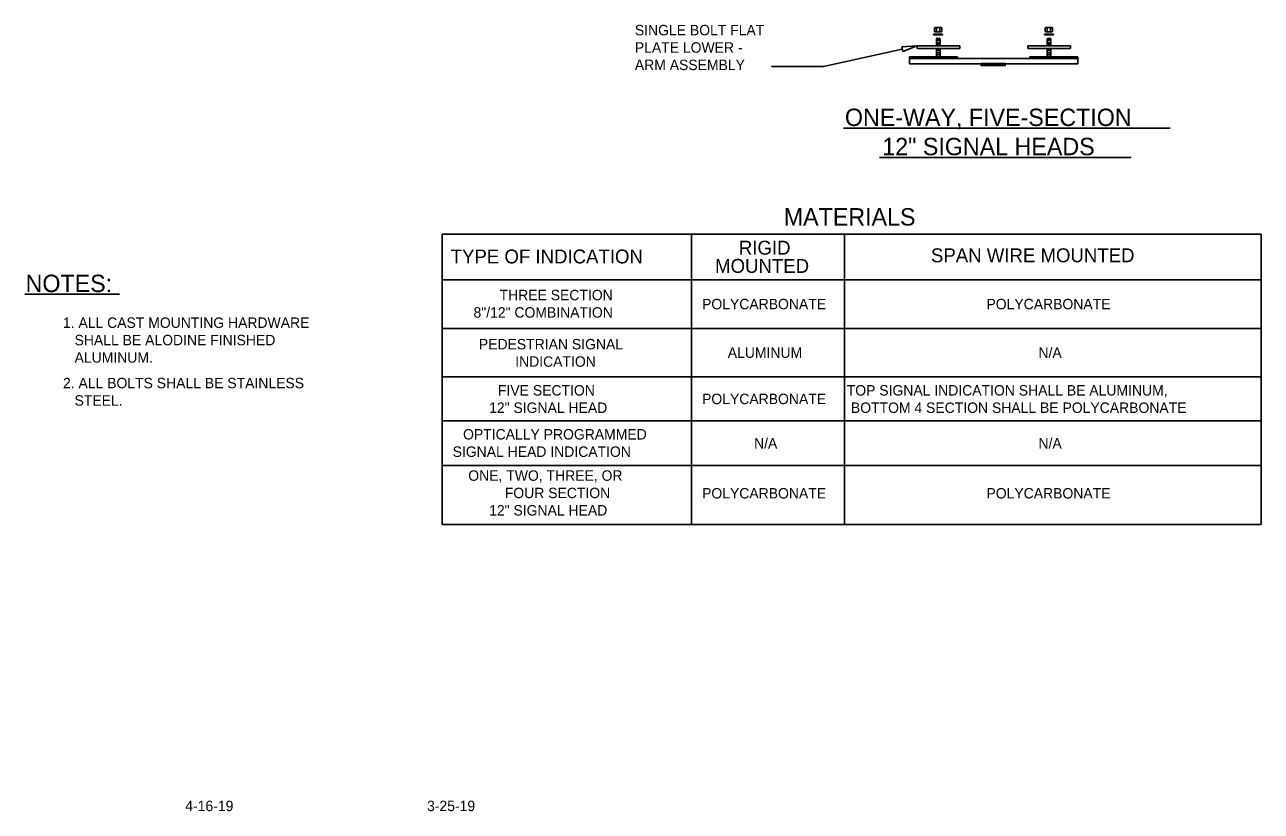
# Model space of a CAD drawing. Extents: x -1316.3 to -1303.1, y 2853.3 to 2863.3.
# Drawn here: x -1316.26 to -1309.14, y 2853.47 to 2857.99 of the extents above; entities that cross this region are included whole.
import ezdxf

# ---------------------------------------------------------------- set-up
doc = ezdxf.new("R2010")
doc.units = 0
for name, color, linetype in [('DETL-DIMS', 7, 'Continuous'), ('DETL-LINE', 7, 'Continuous'), ('DETL-NOTE', 7, 'Continuous'), ('DETL-TITL', 7, 'Continuous'), ('TTLB-TEXT', 7, 'Continuous')]:
    doc.layers.add(name, color=color, linetype=linetype)

msp = doc.modelspace()

# ---------------------------------------------------------------- linework, layer by layer
at = {"layer": 'DETL-DIMS'}
for p, q in [((-1311.2075, 2857.8542), (-1311.6607, 2857.7546)), ((-1311.6607, 2857.7546), (-1311.9592, 2857.7546))]:
    msp.add_line(p, q, dxfattribs=at)
for points in [[(-1311.2107, 2857.8682), (-1311.2043, 2857.8402), (-1311.1219, 2857.873)], [(-1310.7547, 2857.7714), (-1310.6155, 2857.7714), (-1310.6155, 2857.7594), (-1310.7547, 2857.7594)]]:
    msp.add_lwpolyline(points, close=True, dxfattribs=at)
at = {"layer": 'DETL-LINE'}
for p, q in [((-1311.0275, 2857.9402), (-1311.0275, 2857.937)), ((-1311.0275, 2857.9402), (-1310.9755, 2857.9402)), ((-1311.0275, 2857.937), (-1310.9755, 2857.937)), ((-1311.0219, 2857.9762), (-1311.0219, 2857.9562)), ((-1311.0195, 2857.9786), (-1310.9827, 2857.9786)), ((-1311.0195, 2857.9538), (-1310.9827, 2857.9538)), ((-1311.0115, 2857.873), (-1311.0115, 2857.9122)), ((-1311.0107, 2857.9786), (-1311.0107, 2857.9538)), ((-1311.0075, 2857.9162), (-1310.9955, 2857.9162)), ((-1310.9915, 2857.9786), (-1310.9915, 2857.9538)), ((-1310.9907, 2857.873), (-1310.9907, 2857.9122)), ((-1310.9803, 2857.9562), (-1310.9803, 2857.9762)), ((-1310.9755, 2857.9402), (-1310.9755, 2857.937)), ((-1310.3899, 2857.9402), (-1310.3387, 2857.9402)), ((-1310.3899, 2857.9402), (-1310.3899, 2857.937)), ((-1310.3899, 2857.937), (-1310.3387, 2857.937)), ((-1310.3851, 2857.9762), (-1310.3851, 2857.9562)), ((-1310.3827, 2857.9786), (-1310.3459, 2857.9786)), ((-1310.3827, 2857.9538), (-1310.3459, 2857.9538)), ((-1310.3747, 2857.873), (-1310.3747, 2857.9122)), ((-1310.3739, 2857.9786), (-1310.3739, 2857.9538)), ((-1310.3699, 2857.9162), (-1310.3579, 2857.9162)), ((-1310.3547, 2857.9786), (-1310.3547, 2857.9538)), ((-1310.3539, 2857.873), (-1310.3539, 2857.9122)), ((-1310.3435, 2857.9562), (-1310.3435, 2857.9762)), ((-1310.3387, 2857.9402), (-1310.3387, 2857.937)), ((-1311.1219, 2857.8578), (-1311.1219, 2857.873)), ((-1311.1219, 2857.873), (-1310.8771, 2857.873)), ((-1311.1219, 2857.8578), (-1310.8771, 2857.8578)), ((-1311.0115, 2857.905), (-1310.9907, 2857.905)), ((-1311.0115, 2857.893), (-1310.9907, 2857.893)), ((-1311.0115, 2857.8818), (-1310.9907, 2857.8818)), ((-1311.0115, 2857.8146), (-1311.0115, 2857.8578)), ((-1311.0115, 2857.8474), (-1310.9907, 2857.8474)), ((-1310.9907, 2857.8146), (-1310.9907, 2857.8578)), ((-1310.8771, 2857.8578), (-1310.8771, 2857.873)), ((-1310.4851, 2857.873), (-1310.2395, 2857.873)), ((-1310.4851, 2857.8578), (-1310.4851, 2857.873)), ((-1310.4851, 2857.8578), (-1310.2395, 2857.8578)), ((-1310.3747, 2857.905), (-1310.3539, 2857.905)), ((-1310.3747, 2857.893), (-1310.3539, 2857.893)), ((-1310.3747, 2857.8818), (-1310.3539, 2857.8818)), ((-1310.3747, 2857.8146), (-1310.3747, 2857.8578)), ((-1310.3747, 2857.8474), (-1310.3539, 2857.8474)), ((-1310.3539, 2857.8146), (-1310.3539, 2857.8578)), ((-1310.2395, 2857.8578), (-1310.2395, 2857.873)), ((-1311.1659, 2857.7698), (-1311.1659, 2857.8106)), ((-1311.1659, 2857.8106), (-1310.8891, 2857.8106)), ((-1311.1659, 2857.8002), (-1310.1971, 2857.8002)), ((-1311.1659, 2857.7698), (-1310.1971, 2857.7698)), ((-1311.0115, 2857.8354), (-1310.9907, 2857.8354)), ((-1311.0115, 2857.8242), (-1310.9907, 2857.8242)), ((-1311.0091, 2857.8122), (-1310.9931, 2857.8122)), ((-1310.8891, 2857.8002), (-1310.8891, 2857.8106)), ((-1310.4739, 2857.8002), (-1310.4739, 2857.8106)), ((-1310.4739, 2857.8106), (-1310.1971, 2857.8106)), ((-1310.3747, 2857.8354), (-1310.3539, 2857.8354)), ((-1310.3747, 2857.8242), (-1310.3539, 2857.8242)), ((-1310.3723, 2857.8122), (-1310.3555, 2857.8122)), ((-1310.1971, 2857.8106), (-1310.1971, 2857.7698))]:
    msp.add_line(p, q, dxfattribs=at)
for centre, radius, start, end in [((-1311.0196, 2857.9762), 0.00231, 90, 180), ((-1311.0196, 2857.9563), 0.00231, 180, 270), ((-1311.0071, 2857.9118), 0.00462, 90, 180), ((-1310.9956, 2857.9118), 0.00462, 0, 90), ((-1310.9828, 2857.9762), 0.00231, 0, 90), ((-1310.9828, 2857.9563), 0.00231, 270, 0), ((-1310.3827, 2857.9762), 0.00231, 90, 180), ((-1310.3827, 2857.9563), 0.00231, 180, 270), ((-1310.3697, 2857.9118), 0.00462, 90, 180), ((-1310.3581, 2857.9118), 0.00462, 0, 90), ((-1310.3459, 2857.9762), 0.00231, 0, 90), ((-1310.3459, 2857.9563), 0.00231, 270, 0), ((-1311.0094, 2857.8148), 0.00231, 180, 270), ((-1310.9933, 2857.8148), 0.00231, 270, 0), ((-1310.372, 2857.8148), 0.00231, 180, 270), ((-1310.3558, 2857.8148), 0.00231, 270, 0)]:
    msp.add_arc(centre, radius, start, end, dxfattribs=at)
at = {"layer": 'DETL-NOTE'}
for p, q in [((-1313.855, 2855.1203), (-1313.855, 2856.7894)), ((-1313.855, 2856.7894), (-1309.1427, 2856.7894)), ((-1312.4208, 2856.7894), (-1312.4208, 2855.1203)), ((-1311.5406, 2856.7894), (-1311.5406, 2855.1203)), ((-1309.1427, 2856.7894), (-1309.1427, 2855.1203)), ((-1313.855, 2856.5275), (-1309.1427, 2856.5275)), ((-1316.2556, 2856.4441), (-1315.7106, 2856.4441)), ((-1313.855, 2856.248), (-1309.1427, 2856.248)), ((-1313.855, 2855.9686), (-1309.1427, 2855.9686)), ((-1313.855, 2855.7154), (-1309.1427, 2855.7154)), ((-1309.1427, 2855.4583), (-1313.855, 2855.4583)), ((-1309.1427, 2855.1203), (-1313.855, 2855.1203))]:
    msp.add_line(p, q, dxfattribs=at)
at = {"layer": 'DETL-TITL'}
for p, q in [((-1311.5456, 2857.3994), (-1309.666, 2857.3994)), ((-1311.338, 2857.2314), (-1309.8913, 2857.2314))]:
    msp.add_line(p, q, dxfattribs=at)

# ---------------------------------------------------------------- texts
at = {"layer": 'DETL-NOTE'}
for s, height, p in [('SINGLE BOLT FLAT', 0.06, (-1312.746, 2857.9336)), ('PLATE LOWER -', 0.06, (-1312.746, 2857.8336)), ('ARM ASSEMBLY', 0.06, (-1312.746, 2857.7336)), ('MATERIALS', 0.1, (-1311.8896, 2856.8394)), ('RIGID', 0.08, (-1312.1478, 2856.672)), ('SPAN WIRE MOUNTED', 0.08, (-1311.0427, 2856.6282)), ('TYPE OF INDICATION', 0.08, (-1313.8053, 2856.6215)), ('MOUNTED', 0.08, (-1312.2845, 2856.5671)), ('NOTES:', 0.1, (-1316.2506, 2856.4566)), ('THREE SECTION', 0.06, (-1313.5241, 2856.4096)), ('POLYCARBONATE', 0.06, (-1312.3593, 2856.3577)), ('POLYCARBONATE', 0.06, (-1310.7234, 2856.3577)), ('8"/12" COMBINATION', 0.06, (-1313.6741, 2856.3096)), ('1. ALL CAST MOUNTING HARDWARE', 0.06, (-1316.0357, 2856.2506)), ('   SHALL BE ALODINE FINISHED', 0.06, (-1316.0357, 2856.1506)), ('PEDESTRIAN SIGNAL', 0.06, (-1313.6431, 2856.127)), ('ALUMINUM', 0.06, (-1312.2115, 2856.0783)), ('N/A', 0.06, (-1310.4243, 2856.0783)), ('   ALUMINUM.', 0.06, (-1316.0357, 2856.0506)), ('INDICATION', 0.06, (-1313.4342, 2856.027)), ('2. ALL BOLTS SHALL BE STAINLESS', 0.06, (-1316.0357, 2855.9033)), ('FIVE SECTION ', 0.06, (-1313.5333, 2855.8615)), ('TOP SIGNAL INDICATION SHALL BE ALUMINUM,', 0.06, (-1311.5272, 2855.8615)), ('   STEEL.', 0.06, (-1316.0357, 2855.8033)), ('POLYCARBONATE', 0.06, (-1312.3593, 2855.812)), ('12" SIGNAL HEAD', 0.06, (-1313.5842, 2855.7615)), ('BOTTOM 4 SECTION SHALL BE POLYCARBONATE', 0.06, (-1311.5032, 2855.7615)), ('OPTICALLY PROGRAMMED', 0.06, (-1313.7342, 2855.6086)), ('SIGNAL HEAD INDICATION', 0.06, (-1313.7942, 2855.5086)), ('N/A', 0.06, (-1312.0603, 2855.5568)), ('N/A', 0.06, (-1310.4242, 2855.5568)), ('ONE, TWO, THREE, OR ', 0.06, (-1313.7041, 2855.3712)), ('FOUR SECTION ', 0.06, (-1313.4941, 2855.2712)), ('POLYCARBONATE', 0.06, (-1312.3593, 2855.2693)), ('POLYCARBONATE', 0.06, (-1310.7234, 2855.2693)), ('12" SIGNAL HEAD', 0.06, (-1313.5842, 2855.1712))]:
    msp.add_text(s, height=height, dxfattribs=at).set_placement(p)
at = {"layer": 'DETL-TITL'}
for s, p in [('ONE-WAY, FIVE-SECTION', (-1311.5377, 2857.4119)), ('12" SIGNAL HEADS', (-1311.3227, 2857.2439))]:
    msp.add_text(s, height=0.1, dxfattribs=at).set_placement(p)
at = {"layer": 'TTLB-TEXT'}
for s, p in [('4-16-19', (-1315.3319, 2853.4709)), ('3-25-19', (-1313.9414, 2853.4709))]:
    msp.add_text(s, height=0.06, dxfattribs=at).set_placement(p)

doc.saveas('drawing.dxf')
